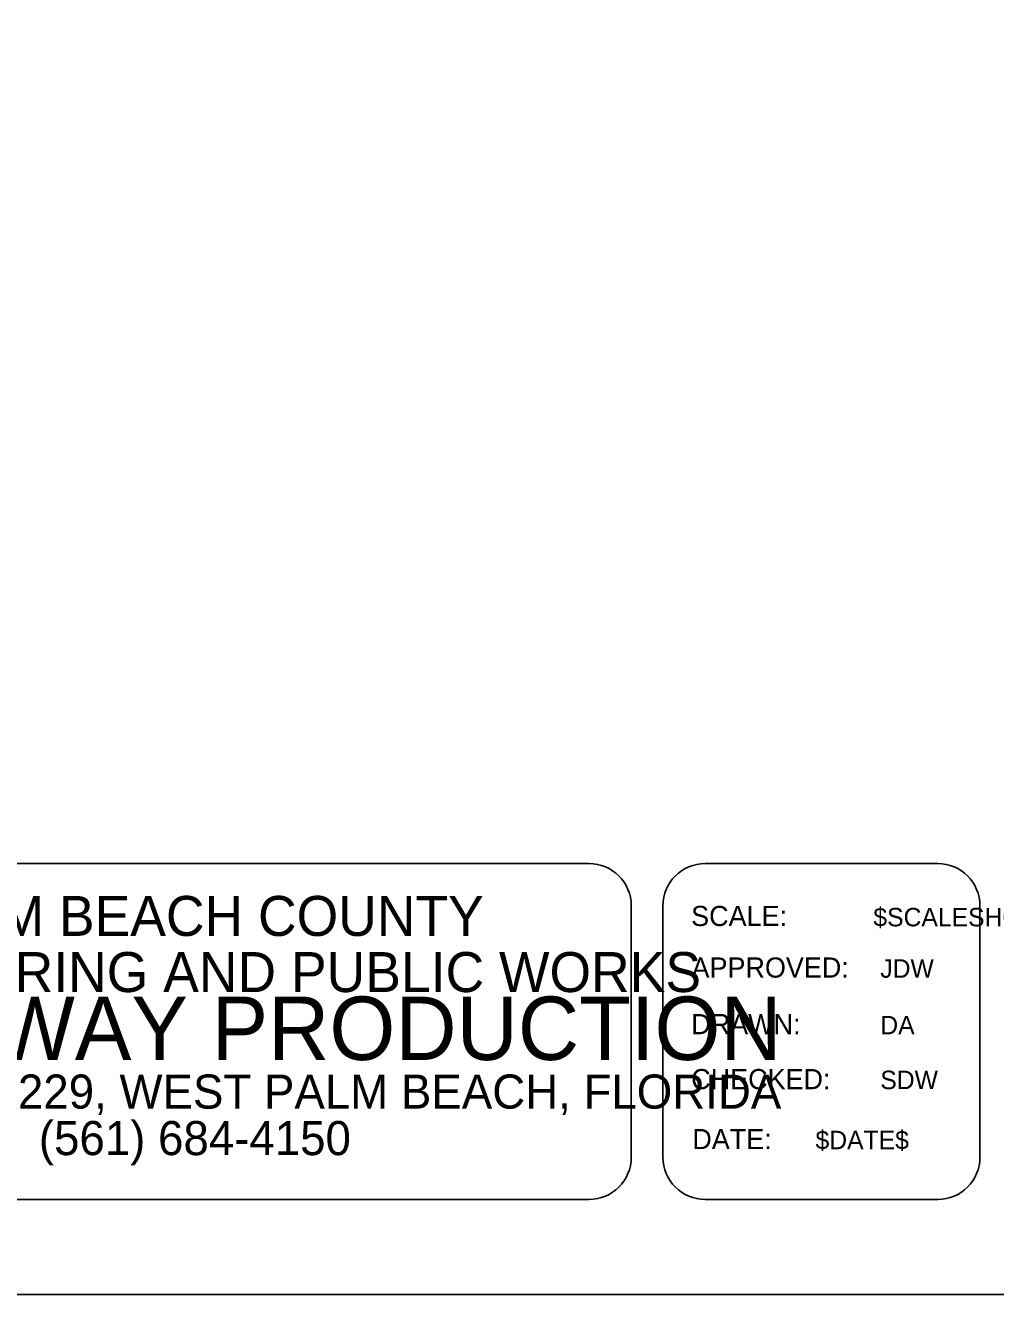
# Model space of a CAD drawing. Extents: x -0.7 to 16, y -0.9 to 9.7.
# Drawn here: x 9.999 to 12.024, y -0.9 to 1.75 of the extents above; entities that cross this region are included whole.
import ezdxf

# ---------------------------------------------------------------- set-up
doc = ezdxf.new("R2010")
doc.units = 0
for name, color, linetype in [('Default', 7, 'Continuous'), ('PlotBorder_dp', 7, 'Continuous'), ('TextLabel', 7, 'Continuous')]:
    doc.layers.add(name, color=color, linetype=linetype)

msp = doc.modelspace()

# ---------------------------------------------------------------- linework, layer by layer
at = {"layer": 'Default'}
for p, q in [((11.1756, 0), (8.7497, 0)), ((11.4182, 0), (11.9034, 0)), ((11.2638, -0.0882), (11.2638, -0.6131)), ((11.33, -0.0882), (11.33, -0.6131)), ((11.9916, -0.0882), (11.9916, -0.6131)), ((11.1756, -0.7014), (8.7497, -0.7014)), ((11.4182, -0.7014), (11.9034, -0.7014))]:
    msp.add_line(p, q, dxfattribs=at)
for centre, major_axis, start_param, end_param in [((11.1756, -0.0882), (0, 0.0882), 4.712389, 6.283185), ((11.4182, -0.0882), (0, 0.0882), 0, 1.570796), ((11.9034, -0.0882), (0, 0.0882), 4.712389, 6.283185), ((11.1756, -0.6131), (0, 0.0882), 3.141593, 4.712389), ((11.4182, -0.6131), (0, -0.0882), 4.712389, 6.283185), ((11.9034, -0.6131), (0, -0.0882), 0, 1.570796)]:
    msp.add_ellipse(centre, major_axis=major_axis, ratio=0.999927, start_param=start_param, end_param=end_param, dxfattribs=at)
at = {"layer": 'PlotBorder_dp'}
msp.add_lwpolyline([(-0.55, -0.9), (15.95, -0.9), (15.95, 9.7), (-0.55, 9.7)], close=True, dxfattribs=at)

# ---------------------------------------------------------------- texts
at = {"layer": 'Default'}
for s, height, p in [('PALM BEACH COUNTY', 0.083446, (9.7345, -0.1511)), ('ENGINEERING AND PUBLIC WORKS', 0.083468, (9.4745, -0.2683)), ('ROADWAY PRODUCTION', 0.132369, (9.4241, -0.4101)), ('P.O. BOX 21229, WEST PALM BEACH, FLORIDA', 0.071224, (9.4333, -0.5117)), ('(561) 684-4150', 0.071224, (10.0274, -0.6088))]:
    msp.add_text(s, height=height, rotation=360, dxfattribs=at).set_placement(p)
for s, height, p in [('SCALE:', 0.04207, (11.3888, -0.1305)), ('APPROVED:', 0.04207, (11.3896, -0.2381)), ('JDW', 0.03855, (11.7836, -0.2384)), ('DRAWN:', 0.04207, (11.389, -0.3563)), ('DA ', 0.03855, (11.7836, -0.3565)), ('CHECKED:', 0.04207, (11.3889, -0.4711)), ('SDW', 0.03855, (11.7836, -0.471)), ('DATE:', 0.04207, (11.3913, -0.5963)), ('$DATE$', 0.03855, (11.6484, -0.5965))]:
    msp.add_text(s, height=height, dxfattribs=at).set_placement(p)
at = {"layer": 'TextLabel'}
msp.add_text('$SCALESHORT$', height=0.038546, dxfattribs=at).set_placement((11.7691, -0.1311))

doc.saveas('drawing.dxf')
